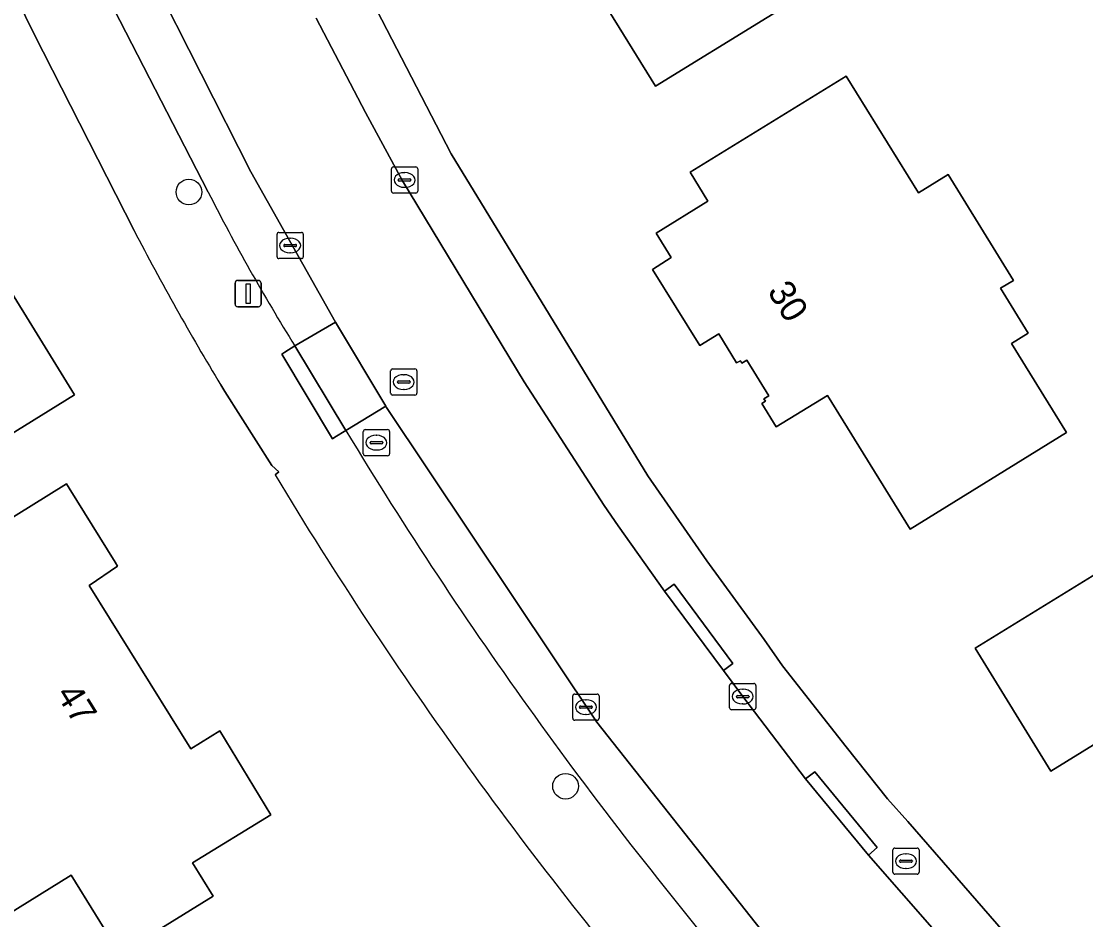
# Model space of a CAD drawing. Extents: x 158835 to 160077, y 386387 to 387778.
# Drawn here: x 159275.32 to 159315.9, y 386661.19 to 386695.46 of the extents above; entities that cross this region are included whole.
import ezdxf

# ---------------------------------------------------------------- set-up
doc = ezdxf.new("R2010")
doc.units = 0
for name, color, linetype in [('IMGEO_Boom', 7, 'Continuous'), ('IMGEO_Brandkraan', 7, 'Continuous'), ('IMGEO_Erf', 7, 'Continuous'), ('IMGEO_Kolk', 7, 'Continuous'), ('IMGEO_Lichtmast', 7, 'Continuous'), ('IMGEO_Pand', 7, 'Continuous'), ('IMGEO_Pand_nummerreeks', 7, 'Continuous'), ('IMGEO_Parkeervlak_open', 7, 'Continuous'), ('IMGEO_Rijbaan_lokaal_gesloten', 7, 'Continuous'), ('IMGEO_Rioolput', 7, 'Continuous'), ('IMGEO_Voetpad_open', 7, 'Continuous')]:
    doc.layers.add(name, color=color, linetype=linetype)

msp = doc.modelspace()

# ---------------------------------------------------------------- linework, layer by layer
at = {"layer": 'IMGEO_Boom'}
for centre in [(159281.714, 386688.943), (159296.07, 386666.283)]:
    msp.add_circle(centre, 0.489, dxfattribs=at)
at = {"layer": 'IMGEO_Brandkraan'}
for p, q in [((159308.546, 386663.001), (159308.546, 386663.853)), ((159308.621, 386663.927), (159309.473, 386663.927)), ((159309.547, 386663.853), (159309.547, 386663.001)), ((159308.805, 386663.421), (159308.805, 386663.433)), ((159308.848, 386663.47), (159309.246, 386663.47)), ((159309.034, 386663.707), (159309.059, 386663.707)), ((159309.289, 386663.433), (159309.289, 386663.421)), ((159309.243, 386663.384), (159308.845, 386663.384)), ((159309.057, 386663.147), (159309.032, 386663.147)), ((159309.473, 386662.927), (159308.621, 386662.927))]:
    msp.add_line(p, q, dxfattribs=at)
for points in [[(159308.546, 386663.001), (159308.546, 386663.853)], [(159308.621, 386663.927), (159309.473, 386663.927)], [(159309.547, 386663.853), (159309.547, 386663.001)], [(159309.473, 386662.927), (159308.621, 386662.927)]]:
    msp.add_lwpolyline(points, dxfattribs=at)
for centre, radius, start, end in [((159308.623, 386663.851), 0.0765, 91.552, 178.448), ((159308.623, 386663.851), 0.0765, 91.552, 178.448), ((159309.471, 386663.851), 0.0765, 1.552, 88.448), ((159309.471, 386663.851), 0.0765, 1.552, 88.448), ((159308.845, 386663.43), 0.0403, 85.8775, 175.7526), ((159308.842, 386663.42), 0.0366, 178.938, 274.7102), ((159309.246, 386663.427), 0.043, 264.8664, 352.4533), ((159309.25, 386663.432), 0.0386, 1.7309, 96.639), ((159308.623, 386663.003), 0.0765, 181.552, 268.448), ((159308.623, 386663.003), 0.0765, 181.552, 268.448), ((159309.471, 386663.003), 0.0765, 271.552, 358.448), ((159309.471, 386663.003), 0.0765, 271.552, 358.448)]:
    msp.add_arc(centre, radius, start, end, dxfattribs=at)
for centre, major_axis, ratio, start_param, end_param in [((159309.033, 386663.427), (-0.387, 0.002), 0.722429, 4.712389, 7.853982), ((159309.058, 386663.427), (-0.39, 0.002), 0.717154, 1.570796, 4.712389)]:
    msp.add_ellipse(centre, major_axis=major_axis, ratio=ratio, start_param=start_param, end_param=end_param, dxfattribs=at)
at = {"layer": 'IMGEO_Erf'}
for points in [[(159291.757, 386726.701), (159285.398, 386711.692), (159285.027, 386710.896), (159284.728, 386710.07), (159284.504, 386709.221), (159284.357, 386708.355), (159284.288, 386707.479), (159284.297, 386706.6), (159284.385, 386705.726), (159284.551, 386704.864), (159284.793, 386704.019), (159285.109, 386703.2), (159285.288, 386702.815), (159291.715, 386690.4), (159299.208, 386678.123), (159301.454, 386674.875), (159303.638, 386671.874), (159304.346, 386670.869), (159306.768, 386667.782), (159308.337, 386665.804), (159309.121, 386664.939), (159314.122, 386659.18)], [(159279.623, 386687.477), (159275.817, 386694.968), (159274.157, 386698.347)], [(159308.016, 386698.233), (159299.496, 386692.978), (159296.496, 386697.842), (159295.536, 386697.238)], [(159284.999, 386678.16), (159285.137, 386678.27), (159284.873, 386678.511), (159283.089, 386681.331), (159282.928, 386681.585)]]:
    msp.add_lwpolyline(points, dxfattribs=at)
for points in [[(159269.86, 386688.668), (159270.766, 386689.22), (159272.124, 386687.031), (159273.306, 386687.757), (159277.357, 386681.213), (159267.545, 386675.138), (159264.169, 386680.627), (159260.869, 386678.598), (159261.048, 386678.307), (159257.115, 386675.888), (159251.173, 386685.55), (159262.23, 386692.216), (159266.455, 386694.89), (159266.966, 386694.064), (159266.592, 386693.832)], [(159313.14, 386685.575), (159312.648, 386685.272), (159313.7, 386683.565), (159313.063, 386683.173), (159315.161, 386679.769), (159309.206, 386676.09), (159306.061, 386681.18), (159304.096, 386679.985), (159303.553, 386680.877), (159303.687, 386680.965), (159303.634, 386681.063), (159303.823, 386681.177), (159302.979, 386682.529), (159302.794, 386682.421), (159302.736, 386682.507), (159302.592, 386682.427), (159301.908, 386683.533), (159301.186, 386683.085), (159299.382, 386685.995), (159300.101, 386686.445), (159299.523, 386687.379), (159301.497, 386688.594), (159300.818, 386689.699), (159306.773, 386693.364), (159309.526, 386688.911), (159310.655, 386689.607)], [(159329.817, 386675.621), (159327.278, 386674.054), (159330.286, 386669.169), (159328.114, 386667.832), (159328.533, 386667.15), (159326.085, 386665.645), (159325.631, 386666.295), (159323.476, 386664.962), (159321.477, 386668.208), (159321.188, 386668.685), (159320.295, 386668.147), (159319.082, 386668.437), (159318.53, 386669.315), (159317.99, 386668.971), (159314.565, 386666.863), (159311.678, 386671.543), (159317.295, 386675.008), (159316.98, 386675.518), (159319.157, 386676.861), (159321.606, 386678.371), (159323.783, 386679.714), (159324.005, 386679.354), (159326.547, 386680.922)], [(159278.898, 386674.829), (159278.994, 386674.674), (159277.918, 386673.944), (159281.782, 386667.704), (159282.888, 386668.398), (159284.842, 386665.194), (159281.845, 386663.367), (159282.633, 386662.095), (159279.081, 386659.894), (159277.226, 386662.887), (159273.597, 386660.638), (159268.627, 386668.659), (159271.688, 386670.556), (159269.928, 386673.396), (159277.051, 386677.81), (159277.151, 386677.648)]]:
    msp.add_lwpolyline(points, close=True, dxfattribs=at)
for centre, radius, start, end in [((159377.095, 386738.279), 109.917, 207.52836, 211.0504), ((159421.392, 386760.217), 159.174, 211.03223, 220.61805)]:
    msp.add_arc(centre, radius, start, end, dxfattribs=at)
at = {"layer": 'IMGEO_Kolk'}
for p, q in [((159289.434, 386688.977), (159289.434, 386689.829)), ((159289.509, 386689.903), (159290.361, 386689.903)), ((159290.435, 386689.829), (159290.435, 386688.977)), ((159289.693, 386689.397), (159289.693, 386689.409)), ((159289.736, 386689.446), (159290.134, 386689.446)), ((159289.922, 386689.683), (159289.947, 386689.683)), ((159290.177, 386689.409), (159290.177, 386689.397)), ((159290.131, 386689.36), (159289.733, 386689.36)), ((159289.945, 386689.123), (159289.92, 386689.123)), ((159290.361, 386688.903), (159289.509, 386688.903)), ((159285.147, 386687.405), (159285.999, 386687.405)), ((159285.072, 386686.479), (159285.072, 386687.331)), ((159285.374, 386686.948), (159285.772, 386686.948)), ((159285.56, 386687.185), (159285.585, 386687.185)), ((159286.073, 386687.331), (159286.073, 386686.479)), ((159285.331, 386686.899), (159285.331, 386686.911)), ((159285.769, 386686.862), (159285.371, 386686.862)), ((159285.583, 386686.625), (159285.558, 386686.625)), ((159285.815, 386686.911), (159285.815, 386686.899)), ((159285.999, 386686.405), (159285.147, 386686.405)), ((159302.322, 386669.276), (159302.322, 386670.128)), ((159302.397, 386670.202), (159303.249, 386670.202)), ((159302.81, 386669.982), (159302.835, 386669.982)), ((159303.323, 386670.128), (159303.323, 386669.276)), ((159296.346, 386668.873), (159296.346, 386669.725)), ((159296.421, 386669.799), (159297.273, 386669.799)), ((159296.834, 386669.579), (159296.859, 386669.579)), ((159297.347, 386669.725), (159297.347, 386668.873)), ((159302.581, 386669.696), (159302.581, 386669.708)), ((159303.019, 386669.659), (159302.621, 386669.659)), ((159302.624, 386669.745), (159303.022, 386669.745)), ((159303.065, 386669.708), (159303.065, 386669.696)), ((159296.605, 386669.293), (159296.605, 386669.305)), ((159297.043, 386669.256), (159296.645, 386669.256)), ((159296.648, 386669.342), (159297.046, 386669.342)), ((159297.089, 386669.305), (159297.089, 386669.293)), ((159303.249, 386669.202), (159302.397, 386669.202)), ((159302.833, 386669.422), (159302.808, 386669.422)), ((159297.273, 386668.799), (159296.421, 386668.799)), ((159296.857, 386669.019), (159296.832, 386669.019))]:
    msp.add_line(p, q, dxfattribs=at)
for points in [[(159289.434, 386688.977), (159289.434, 386689.829)], [(159289.509, 386689.903), (159290.361, 386689.903)], [(159290.435, 386689.829), (159290.435, 386688.977)], [(159290.361, 386688.903), (159289.509, 386688.903)], [(159285.147, 386687.405), (159285.999, 386687.405)], [(159285.072, 386686.479), (159285.072, 386687.331)], [(159286.073, 386687.331), (159286.073, 386686.479)], [(159285.999, 386686.405), (159285.147, 386686.405)], [(159302.322, 386669.276), (159302.322, 386670.128)], [(159302.397, 386670.202), (159303.249, 386670.202)], [(159303.323, 386670.128), (159303.323, 386669.276)], [(159296.346, 386668.873), (159296.346, 386669.725)], [(159296.421, 386669.799), (159297.273, 386669.799)], [(159297.347, 386669.725), (159297.347, 386668.873)], [(159303.249, 386669.202), (159302.397, 386669.202)], [(159297.273, 386668.799), (159296.421, 386668.799)]]:
    msp.add_lwpolyline(points, dxfattribs=at)
for centre, radius, start, end in [((159289.511, 386689.827), 0.0765, 91.552, 178.448), ((159289.511, 386689.827), 0.0765, 91.552, 178.448), ((159290.359, 386689.827), 0.0765, 1.552, 88.448), ((159290.359, 386689.827), 0.0765, 1.552, 88.448), ((159289.733, 386689.406), 0.0403, 85.8775, 175.7526), ((159289.73, 386689.396), 0.0366, 178.938, 274.7102), ((159290.134, 386689.403), 0.043, 264.8664, 352.4533), ((159290.138, 386689.408), 0.0386, 1.7309, 96.639), ((159289.511, 386688.979), 0.0765, 181.552, 268.448), ((159289.511, 386688.979), 0.0765, 181.552, 268.448), ((159290.359, 386688.979), 0.0765, 271.552, 358.448), ((159290.359, 386688.979), 0.0765, 271.552, 358.448), ((159285.149, 386687.329), 0.0765, 91.552, 178.448), ((159285.149, 386687.329), 0.0765, 91.552, 178.448), ((159285.997, 386687.329), 0.0765, 1.552, 88.448), ((159285.997, 386687.329), 0.0765, 1.552, 88.448), ((159285.371, 386686.908), 0.0403, 85.8775, 175.7526), ((159285.776, 386686.91), 0.0386, 1.7309, 96.639), ((159285.368, 386686.898), 0.0366, 178.938, 274.7102), ((159285.772, 386686.905), 0.043, 264.8664, 352.4533), ((159285.149, 386686.481), 0.0765, 181.552, 268.448), ((159285.149, 386686.481), 0.0765, 181.552, 268.448), ((159285.997, 386686.481), 0.0765, 271.552, 358.448), ((159285.997, 386686.481), 0.0765, 271.552, 358.448), ((159302.399, 386670.126), 0.0765, 91.552, 178.448), ((159302.399, 386670.126), 0.0765, 91.552, 178.448), ((159303.247, 386670.126), 0.0765, 1.552, 88.448), ((159303.247, 386670.126), 0.0765, 1.552, 88.448), ((159296.423, 386669.723), 0.0765, 91.552, 178.448), ((159296.423, 386669.723), 0.0765, 91.552, 178.448), ((159297.271, 386669.723), 0.0765, 1.552, 88.448), ((159297.271, 386669.723), 0.0765, 1.552, 88.448), ((159302.621, 386669.705), 0.0403, 85.8775, 175.7526), ((159302.618, 386669.695), 0.0366, 178.938, 274.7102), ((159303.022, 386669.702), 0.043, 264.8664, 352.4533), ((159303.026, 386669.707), 0.0386, 1.7309, 96.639), ((159296.645, 386669.302), 0.0403, 85.8775, 175.7526), ((159296.642, 386669.292), 0.0366, 178.938, 274.7102), ((159297.046, 386669.299), 0.043, 264.8664, 352.4533), ((159297.05, 386669.304), 0.0386, 1.7309, 96.639), ((159302.399, 386669.278), 0.0765, 181.552, 268.448), ((159302.399, 386669.278), 0.0765, 181.552, 268.448), ((159303.247, 386669.278), 0.0765, 271.552, 358.448), ((159303.247, 386669.278), 0.0765, 271.552, 358.448), ((159296.423, 386668.875), 0.0765, 181.552, 268.448), ((159296.423, 386668.875), 0.0765, 181.552, 268.448), ((159297.271, 386668.875), 0.0765, 271.552, 358.448), ((159297.271, 386668.875), 0.0765, 271.552, 358.448)]:
    msp.add_arc(centre, radius, start, end, dxfattribs=at)
for centre, major_axis, ratio, start_param, end_param in [((159289.921, 386689.403), (-0.387, 0.002), 0.722429, 4.712389, 7.853982), ((159289.946, 386689.403), (-0.39, 0.002), 0.717154, 1.570796, 4.712389), ((159285.559, 386686.905), (-0.387, 0.002), 0.722429, 4.712389, 7.853982), ((159285.584, 386686.905), (-0.39, 0.002), 0.717154, 1.570796, 4.712389), ((159302.809, 386669.702), (-0.387, 0.002), 0.722429, 4.712389, 7.853982), ((159302.834, 386669.702), (-0.39, 0.002), 0.717154, 1.570796, 4.712389), ((159296.833, 386669.299), (-0.387, 0.002), 0.722429, 4.712389, 7.853982), ((159296.858, 386669.299), (-0.39, 0.002), 0.717154, 1.570796, 4.712389)]:
    msp.add_ellipse(centre, major_axis=major_axis, ratio=ratio, start_param=start_param, end_param=end_param, dxfattribs=at)
at = {"layer": 'IMGEO_Lichtmast'}
for p, q in [((159283.475, 386684.672), (159283.475, 386685.472)), ((159283.475, 386685.472), (159283.475, 386684.672)), ((159283.575, 386685.572), (159284.365, 386685.572)), ((159284.365, 386685.572), (159283.575, 386685.572)), ((159284.465, 386685.472), (159284.465, 386684.672)), ((159284.465, 386684.672), (159284.465, 386685.472)), ((159284.365, 386684.572), (159283.575, 386684.572)), ((159283.575, 386684.572), (159284.365, 386684.572))]:
    msp.add_line(p, q, dxfattribs=at)
msp.add_lwpolyline([(159283.895, 386685.447), (159284.045, 386685.447), (159284.045, 386684.697), (159283.895, 386684.697), (159283.895, 386685.447)], dxfattribs=at)
for centre, start, end in [((159283.575, 386685.472), 90, 180), ((159283.575, 386685.472), 90, 180), ((159284.365, 386685.472), 0, 90), ((159284.365, 386685.472), 360, 90), ((159283.575, 386684.672), 180, 270), ((159283.575, 386684.672), 180, 270), ((159284.365, 386684.672), 270, 0), ((159284.365, 386684.672), 270, 0)]:
    msp.add_arc(centre, 0.1, start, end, dxfattribs=at)
at = {"layer": 'IMGEO_Pand'}
msp.add_lwpolyline([(159295.536, 386697.238), (159296.496, 386697.842), (159299.496, 386692.978), (159308.016, 386698.233), (159300.468, 386710.457), (159304.926, 386713.21), (159302.078, 386717.823), (159304.218, 386722.599), (159298.628, 386727.367), (159294.985, 386719.024), (159294.178, 386719.374), (159292.114, 386714.607), (159293.768, 386711.923), (159289.858, 386709.5), (159290.379, 386708.645), (159289.448, 386708.074), (159289.847, 386707.437), (159290.847, 386708.063), (159291.826, 386706.448), (159290.822, 386705.829), (159293.486, 386701.509), (159293.089, 386701.303)], dxfattribs=at)
for points in [[(159267.545, 386675.138), (159277.357, 386681.213), (159273.306, 386687.757), (159272.124, 386687.031), (159270.766, 386689.22), (159269.86, 386688.668), (159266.592, 386693.832), (159266.966, 386694.064), (159266.455, 386694.89), (159262.23, 386692.216), (159251.173, 386685.55), (159257.115, 386675.888), (159261.048, 386678.307), (159260.869, 386678.598), (159264.169, 386680.627)], [(159304.096, 386679.985), (159306.061, 386681.18), (159309.206, 386676.09), (159315.161, 386679.769), (159313.063, 386683.173), (159313.7, 386683.565), (159312.648, 386685.272), (159313.14, 386685.575), (159310.655, 386689.607), (159309.526, 386688.911), (159306.773, 386693.364), (159300.818, 386689.699), (159301.497, 386688.594), (159299.523, 386687.379), (159300.101, 386686.445), (159299.382, 386685.995), (159301.186, 386683.085), (159301.908, 386683.533), (159302.592, 386682.427), (159302.736, 386682.507), (159302.794, 386682.421), (159302.979, 386682.529), (159303.823, 386681.177), (159303.634, 386681.063), (159303.687, 386680.965), (159303.553, 386680.877)], [(159327.278, 386674.054), (159329.817, 386675.621), (159326.547, 386680.922), (159324.005, 386679.354), (159323.783, 386679.714), (159321.606, 386678.371), (159319.157, 386676.861), (159316.98, 386675.518), (159317.295, 386675.008), (159311.678, 386671.543), (159314.565, 386666.863), (159317.99, 386668.971), (159318.53, 386669.315), (159319.082, 386668.437), (159320.295, 386668.147), (159321.188, 386668.685), (159321.477, 386668.208), (159323.476, 386664.962), (159325.631, 386666.295), (159326.085, 386665.645), (159328.533, 386667.15), (159328.114, 386667.832), (159330.286, 386669.169)], [(159278.898, 386674.829), (159277.151, 386677.648), (159277.051, 386677.81), (159269.928, 386673.396), (159271.688, 386670.556), (159268.627, 386668.659), (159273.597, 386660.638), (159277.226, 386662.887), (159279.081, 386659.894), (159282.633, 386662.095), (159281.845, 386663.367), (159284.842, 386665.194), (159282.888, 386668.398), (159281.782, 386667.704), (159277.918, 386673.944), (159278.994, 386674.674)]]:
    msp.add_lwpolyline(points, close=True, dxfattribs=at)
at = {"layer": 'IMGEO_Parkeervlak_open'}
for points in [[(159280.284, 386697.196), (159278.638, 386696.363), (159282.453, 386688.933)], [(159285.752, 386683.075), (159287.3, 386683.98), (159284.075, 386689.709), (159280.284, 386697.196)], [(159297.263, 386668.731), (159289.242, 386680.733), (159289.215, 386680.779), (159287.699, 386679.848)], [(159311.772, 386651.715), (159311.528, 386651.956), (159308.966, 386654.479), (159304.162, 386659.994), (159297.263, 386668.731)]]:
    msp.add_lwpolyline(points, dxfattribs=at)
for centre, radius, start, end in [((159352.797, 386724.69), 78.91, 206.94502, 211.82806), ((159427.547, 386764.38), 163.411, 211.15101, 220.30929)]:
    msp.add_arc(centre, radius, start, end, dxfattribs=at)
at = {"layer": 'IMGEO_Rijbaan_lokaal_gesloten'}
for points in [[(159280.612, 386718.433), (159278.924, 386714.373), (159278.82, 386714.122), (159278.269, 386712.801), (159277.838, 386711.435), (159277.648, 386710.642), (159277.389, 386709.226), (159277.258, 386707.793), (159277.256, 386706.354), (159277.382, 386704.921), (159277.636, 386703.504), (159278.015, 386702.116), (159278.516, 386700.767), (159278.609, 386700.563), (159278.878, 386699.974), (159280.284, 386697.196), (159284.075, 386689.709), (159287.3, 386683.98), (159289.215, 386680.779), (159289.242, 386680.733), (159297.263, 386668.731), (159304.162, 386659.994)], [(159312.743, 386657.805), (159307.616, 386663.65), (159305.212, 386666.564), (159302.822, 386669.701), (159302.089, 386670.692), (159299.845, 386673.724), (159298.08, 386676.211), (159297.54, 386676.987), (159294.493, 386681.712), (159289.859, 386689.376), (159288.449, 386691.977), (159286.568, 386695.579)]]:
    msp.add_lwpolyline(points, dxfattribs=at)
at = {"layer": 'IMGEO_Rioolput'}
for p, q in [((159289.404, 386681.272), (159289.404, 386682.124)), ((159289.479, 386682.198), (159290.331, 386682.198)), ((159290.405, 386682.124), (159290.405, 386681.272)), ((159289.663, 386681.692), (159289.663, 386681.704)), ((159289.706, 386681.741), (159290.104, 386681.741)), ((159289.892, 386681.978), (159289.917, 386681.978)), ((159290.147, 386681.704), (159290.147, 386681.692)), ((159290.101, 386681.655), (159289.703, 386681.655)), ((159289.915, 386681.418), (159289.89, 386681.418)), ((159290.331, 386681.198), (159289.479, 386681.198)), ((159288.362, 386678.96), (159288.362, 386679.812)), ((159288.437, 386679.886), (159289.289, 386679.886)), ((159288.85, 386679.666), (159288.875, 386679.666)), ((159289.363, 386679.812), (159289.363, 386678.96)), ((159288.621, 386679.38), (159288.621, 386679.392)), ((159289.059, 386679.343), (159288.661, 386679.343)), ((159288.664, 386679.429), (159289.062, 386679.429)), ((159289.105, 386679.392), (159289.105, 386679.38)), ((159289.289, 386678.886), (159288.437, 386678.886)), ((159288.873, 386679.106), (159288.848, 386679.106))]:
    msp.add_line(p, q, dxfattribs=at)
for points in [[(159289.404, 386681.272), (159289.404, 386682.124)], [(159289.479, 386682.198), (159290.331, 386682.198)], [(159290.405, 386682.124), (159290.405, 386681.272)], [(159290.331, 386681.198), (159289.479, 386681.198)], [(159288.362, 386678.96), (159288.362, 386679.812)], [(159288.437, 386679.886), (159289.289, 386679.886)], [(159289.363, 386679.812), (159289.363, 386678.96)], [(159289.289, 386678.886), (159288.437, 386678.886)]]:
    msp.add_lwpolyline(points, dxfattribs=at)
for centre, radius, start, end in [((159289.481, 386682.122), 0.0765, 91.552, 178.448), ((159289.481, 386682.122), 0.0765, 91.552, 178.448), ((159290.329, 386682.122), 0.0765, 1.552, 88.448), ((159290.329, 386682.122), 0.0765, 1.552, 88.448), ((159289.703, 386681.701), 0.0403, 85.8775, 175.7526), ((159289.7, 386681.691), 0.0366, 178.938, 274.7102), ((159290.104, 386681.698), 0.043, 264.8664, 352.4533), ((159290.108, 386681.703), 0.0386, 1.7309, 96.639), ((159289.481, 386681.274), 0.0765, 181.552, 268.448), ((159289.481, 386681.274), 0.0765, 181.552, 268.448), ((159290.329, 386681.274), 0.0765, 271.552, 358.448), ((159290.329, 386681.274), 0.0765, 271.552, 358.448), ((159288.439, 386679.81), 0.0765, 91.552, 178.448), ((159288.439, 386679.81), 0.0765, 91.552, 178.448), ((159289.287, 386679.81), 0.0765, 1.552, 88.448), ((159289.287, 386679.81), 0.0765, 1.552, 88.448), ((159288.661, 386679.389), 0.0403, 85.8775, 175.7526), ((159288.658, 386679.379), 0.0366, 178.938, 274.7102), ((159289.062, 386679.386), 0.043, 264.8664, 352.4533), ((159289.066, 386679.391), 0.0386, 1.7309, 96.639), ((159288.439, 386678.962), 0.0765, 181.552, 268.448), ((159288.439, 386678.962), 0.0765, 181.552, 268.448), ((159289.287, 386678.962), 0.0765, 271.552, 358.448), ((159289.287, 386678.962), 0.0765, 271.552, 358.448)]:
    msp.add_arc(centre, radius, start, end, dxfattribs=at)
for centre, major_axis, ratio, start_param, end_param in [((159289.891, 386681.698), (-0.387, 0.002), 0.722429, 4.712389, 7.853982), ((159289.916, 386681.698), (-0.39, 0.002), 0.717154, 1.570796, 4.712389), ((159288.849, 386679.386), (-0.387, 0.002), 0.722429, 4.712389, 7.853982), ((159288.874, 386679.386), (-0.39, 0.002), 0.717154, 1.570796, 4.712389)]:
    msp.add_ellipse(centre, major_axis=major_axis, ratio=ratio, start_param=start_param, end_param=end_param, dxfattribs=at)
at = {"layer": 'IMGEO_Voetpad_open'}
for points in [[(159314.122, 386659.18), (159309.121, 386664.939), (159308.337, 386665.804), (159306.768, 386667.782), (159304.346, 386670.869), (159303.638, 386671.874), (159301.454, 386674.875), (159299.208, 386678.123), (159291.715, 386690.4), (159285.288, 386702.815)], [(159282.453, 386688.933), (159278.638, 386696.363), (159278.226, 386696.173), (159278.109, 386696.119), (159276.489, 386699.502), (159277.014, 386699.755)], [(159274.157, 386698.347), (159275.817, 386694.968), (159279.623, 386687.477)], [(159286.568, 386695.579), (159288.449, 386691.977), (159289.859, 386689.376), (159294.493, 386681.712), (159297.54, 386676.987), (159298.08, 386676.211), (159299.845, 386673.724), (159300.213, 386673.992), (159302.445, 386670.968), (159302.089, 386670.692), (159302.822, 386669.701), (159305.212, 386666.564), (159305.567, 386666.828), (159307.949, 386663.943), (159307.616, 386663.65), (159312.743, 386657.805)], [(159287.699, 386679.848), (159287.28, 386679.597), (159287.182, 386679.538), (159285.252, 386682.759), (159285.368, 386682.832), (159285.752, 386683.075)], [(159282.928, 386681.585), (159283.089, 386681.331), (159284.873, 386678.511), (159285.137, 386678.27), (159284.999, 386678.16)]]:
    msp.add_lwpolyline(points, dxfattribs=at)
for points in [[(159287.3, 386683.98), (159285.752, 386683.075), (159287.699, 386679.848), (159289.215, 386680.779)], [(159285.752, 386683.075), (159285.368, 386682.832), (159285.252, 386682.759), (159287.182, 386679.538), (159287.28, 386679.597), (159287.699, 386679.848)], [(159299.845, 386673.724), (159302.089, 386670.692), (159302.445, 386670.968), (159300.213, 386673.992)], [(159305.212, 386666.564), (159307.616, 386663.65), (159307.949, 386663.943), (159305.567, 386666.828)]]:
    msp.add_lwpolyline(points, close=True, dxfattribs=at)
for centre, radius, start, end in [((159352.797, 386724.69), 78.91, 206.94502, 211.82806), ((159377.095, 386738.279), 109.917, 207.52836, 211.0504), ((159427.547, 386764.38), 163.411, 211.15101, 220.30929), ((159421.392, 386760.217), 159.174, 211.03223, 220.61805)]:
    msp.add_arc(centre, radius, start, end, dxfattribs=at)

# ---------------------------------------------------------------- texts
at = {"layer": 'IMGEO_Pand_nummerreeks'}
for s, rotation, p in [('30', 301.7885, (159303.742, 386685.157)), ('47', 301.7671, (159276.626, 386669.8))]:
    msp.add_text(s, height=1, rotation=rotation, dxfattribs=at).set_placement(p)

doc.saveas('drawing.dxf')
